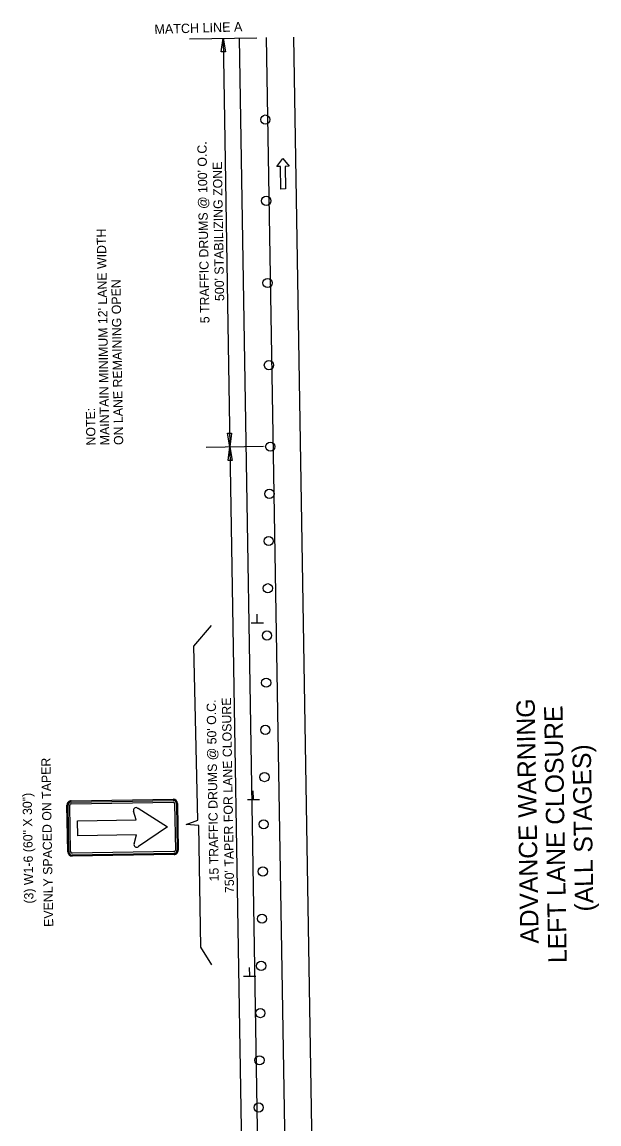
# Model space of a CAD drawing. Extents: x 1676063 to 1678026, y 228339 to 229904.
# Drawn here: x 1676129 to 1676505, y 229116 to 229833 of the extents above; entities that cross this region are included whole.
import ezdxf

# ---------------------------------------------------------------- set-up
doc = ezdxf.new("R2010")
doc.units = 0
for name, color, linetype in [('Default', 7, 'Continuous'), ('P_TC_Signs_Permanent', 7, 'Continuous'), ('R_Annotation', 7, 'Continuous'), ('R_MOT', 7, 'Continuous')]:
    doc.layers.add(name, color=color, linetype=linetype)

msp = doc.modelspace()

# ---------------------------------------------------------------- linework, layer by layer
at = {"layer": 'Default'}
for p, q in [((1676300.39, 229096.37), (1676288.34, 229823.3)), ((1676318.12, 229096.67), (1676306.07, 229823.59)), ((1676238.05, 229822.47), (1676281.96, 229823.19)), ((1676258.82, 229813.94), (1676260, 229822.83)), ((1676260, 229822.83), (1676264.41, 229556.88)), ((1676260, 229822.83), (1676261.48, 229813.99)), ((1676282.66, 229096.08), (1676270.61, 229823.01)), ((1676261.48, 229813.99), (1676258.82, 229813.94)), ((1676262.93, 229565.73), (1676265.59, 229565.77)), ((1676264.41, 229556.88), (1676262.93, 229565.73)), ((1676265.59, 229565.77), (1676264.41, 229556.88)), ((1676249.07, 229556.63), (1676286.37, 229557.25)), ((1676263.23, 229548), (1676264.41, 229556.88)), ((1676264.41, 229556.88), (1676272.05, 229095.9)), ((1676264.41, 229556.88), (1676265.89, 229548.04)), ((1676265.89, 229548.04), (1676263.23, 229548)), ((1676282.22, 229442.46), (1676282.13, 229447.91)), ((1676278.25, 229442.28), (1676286.23, 229442.41)), ((1676279.78, 229327.45), (1676279.69, 229332.89)), ((1676275.81, 229327.26), (1676283.79, 229327.4)), ((1676277.33, 229212.43), (1676277.24, 229217.88)), ((1676273.37, 229212.25), (1676281.35, 229212.38))]:
    msp.add_line(p, q, dxfattribs=at)
msp.add_lwpolyline([(1676252.74, 229219.58), (1676245.6, 229231.28), (1676244.28, 229310.47), (1676235.93, 229311.03), (1676243.53, 229313.93), (1676240.96, 229427.15), (1676252.56, 229440.55)], dxfattribs=at)
for centre in [(1676287.48, 229769.92), (1676288.09, 229717.02), (1676288.97, 229663.56), (1676289.85, 229610.09), (1676290.73, 229557.01), (1676290.19, 229526.29), (1676289.66, 229495.56), (1676289.12, 229464.83), (1676288.58, 229434.1), (1676288.04, 229403.37), (1676287.5, 229372.64), (1676286.97, 229341.91), (1676286.43, 229311.18), (1676285.89, 229280.45), (1676285.35, 229249.73), (1676284.81, 229219), (1676284.27, 229188.27), (1676283.74, 229157.54), (1676283.2, 229126.81)]:
    msp.add_circle(centre, 3, dxfattribs=at)
at = {"layer": 'P_TC_Signs_Permanent'}
for p, q in [((1676158.83, 229293.18), (1676158.33, 229323.55)), ((1676159.58, 229293.19), (1676159.08, 229323.56)), ((1676160.71, 229293.21), (1676160.2, 229323.58)), ((1676161.09, 229326.41), (1676227.46, 229327.51)), ((1676161.11, 229325.66), (1676227.47, 229326.76)), ((1676161.13, 229324.53), (1676227.49, 229325.63)), ((1676228.44, 229324.71), (1676228.95, 229294.34)), ((1676229.57, 229324.73), (1676230.07, 229294.36)), ((1676230.32, 229324.74), (1676230.82, 229294.37)), ((1676228.03, 229293.39), (1676161.66, 229292.29)), ((1676228.04, 229292.26), (1676161.68, 229291.16)), ((1676228.06, 229291.51), (1676161.69, 229290.41))]:
    msp.add_line(p, q, dxfattribs=at)
for points in [[(1676204.62, 229321.57), (1676223.82, 229309.45), (1676205.03, 229296.73)], [(1676202.05, 229298.45), (1676203.67, 229304.24), (1676165.41, 229303.6), (1676165.25, 229313.35), (1676203.51, 229313.99), (1676201.66, 229319.7)]]:
    msp.add_lwpolyline(points, dxfattribs=at)
for centre, radius, start, end in [((1676161.14, 229323.6), 2.81, 90.94971, 180.94971), ((1676161.14, 229323.6), 2.06, 90.94971, 180.94971), ((1676161.14, 229323.6), 0.938, 90.94971, 180.94971), ((1676203.38, 229320.23), 1.8, 57.47423, 196.91879), ((1676244.68, 229384.98), 75, 237.47423, 237.72111), ((1676227.51, 229324.7), 2.81, 0.94971, 90.94971), ((1676227.51, 229324.7), 2.06, 0.94971, 90.94971), ((1676227.51, 229324.7), 0.938, 0.94971, 90.94971), ((1676161.64, 229293.23), 2.81, 180.94971, 270.94971), ((1676161.64, 229293.23), 2.06, 180.94971, 270.94971), ((1676161.64, 229293.23), 0.937, 180.94971, 270.94971), ((1676203.75, 229297.99), 1.76, 164.98063, 304.35028), ((1676247.07, 229234.62), 75, 124.09274, 124.35028), ((1676228.01, 229294.33), 0.938, 270.94971, 0.94971), ((1676228.01, 229294.33), 2.06, 270.94971, 0.94971), ((1676228.01, 229294.33), 2.81, 270.94971, 0.94971)]:
    msp.add_arc(centre, radius, start, end, dxfattribs=at)
at = {"layer": 'R_MOT'}
msp.add_lwpolyline([(1676294.94, 229739.38), (1676298.86, 229744.64), (1676302.94, 229739.51), (1676300.44, 229739.47), (1676300.67, 229724.76), (1676297.67, 229724.71), (1676297.44, 229739.42)], close=True, dxfattribs=at)

# ---------------------------------------------------------------- texts
at = {"layer": 'R_Annotation'}
for s, height, rotation, p in [('     MATCH LINE A', 6.1199, 1.75564, (1676204.01, 229825.29)), ("5 TRAFFIC DRUMS @ 100' O.C.", 6, 90.94971, (1676251.16, 229637.39)), ("500' STABILIZING ZONE", 6, 90.94971, (1676260.75, 229651.88)), ("MAINTAIN MINIMUM 12' LANE WIDTH", 6, 90.94971, (1676185.98, 229557.97)), ('ON LANE REMAINING OPEN', 6, 90.94971, (1676194.98, 229558.12)), ('NOTE:', 6, 90.94971, (1676176.98, 229557.82)), ("750' TAPER FOR LANE CLOSURE", 6, 90.94971, (1676267.24, 229266.47)), ("15 TRAFFIC DRUMS @ 50' O.C.", 6, 90.94971, (1676257.19, 229274.01)), ('ADVANCE WARNING', 12, 90.94971, (1676465.57, 229233.54)), ('LEFT LANE CLOSURE', 12, 90.94971, (1676483.78, 229220.94)), ('(ALL STAGES)', 12, 90.94971, (1676501.23, 229254.5)), ('EVENLY SPACED ON TAPER', 6, 90.95726, (1676149.42, 229244.44)), ('(3) W1-6 (60" X 30")', 6, 90.95726, (1676136.57, 229259.61))]:
    msp.add_text(s, height=height, rotation=rotation, dxfattribs=at).set_placement(p)

doc.saveas('drawing.dxf')
